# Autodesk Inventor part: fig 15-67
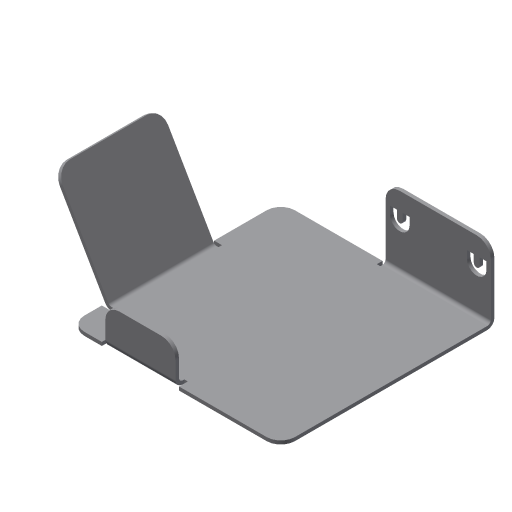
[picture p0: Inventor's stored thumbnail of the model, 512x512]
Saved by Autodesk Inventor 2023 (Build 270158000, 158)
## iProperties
Created: 2002-04
Part Number: fig 15-67
Document SubType Name: Sheet Metal
Density: 1 g/cm^3
Sheet Metal Rule: Default
Material: Generic
Appearance: Default
Control State: 0
Master: False
Checked Out: False
Shininess: 77.0
Angle Display Precision: 2
Document Length Units: 11269
Document Angle Units: 11279
Document Time Units: 11290
Document Mass Units: 11283
Document Length Units Precision: 3
Document Angle Units Precision: 2
Density: 0.0
Volumn: 0.0
Area: 0.0
PropertySet Name: Model Information
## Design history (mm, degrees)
node "Face1"
  sketch "Sketch1"
    geometry: L1 (12.647, 25.882)-(12.647, -14.118); L2 (12.647, -14.118)-(-17.353, -14.118); L3 (-17.353, -14.118)-(-17.353, 15.882); L4 (-17.353, 15.882)-(-2.353, 15.882); L5 (-2.353, 15.882)-(-2.353, 25.882); L6 (-2.353, 25.882)-(12.647, 25.882); 1 further point
    constraints: 12 end point, 4 parallel, 1 perpendicular
    dimensions: "d5" = 30 distance of L2.end L3.end; "d6" = 10 distance of L4.end L5.end; "d7" = 15 distance of L3.end L4.end; "d25" = 15 distance of L5.end L1.start
sketch "Sketch3"
  geometry: L1 (10, -15)-(10, 0)
  constraints: 2 end point
feature "Fold3" sketch "Sketch3" dims "d26" = 0.5 (= BendRadius), "d27" = 90 deg, "d28" = 0.5 (= BendRadius), "d96" = 0.5 (= BendReliefWidth), "d97" = 0.25 (= BendReliefDepth), "d98" = 1 (= MinimumRemnant), "d108" = 0.5 (= Thickness), "SeamGap" = 0.01
node "Flange2"
sketch "Sketch6"
  geometry: L1 (-6.914, 3.413)-(-5.843, 3.413); L2 (-5.843, 0.624)-(-6.914, 0.624); L3 (-6.914, 2.432)-(-5.843, 2.432); L4 (-5.843, 1.605)-(-6.914, 1.605); L5 (-6.914, 0.624)-(-6.914, 1.605); L6 (-6.914, 2.432)-(-6.914, 3.413); L7 (-6.914, 12.568)-(-6.914, 11.587); L8 (-6.914, 14.376)-(-6.914, 13.395); L9 (-6.914, 11.587)-(-5.843, 11.587); L10 (-5.843, 14.376)-(-6.914, 14.376); L11 (-6.914, 12.568)-(-5.843, 12.568); L12 (-5.843, 13.395)-(-6.914, 13.395); A1 r 1.394 centre (-5.843, 2.018) between (-5.843, 0.624) and (-5.843, 3.413); A2 r 0.413 centre (-5.843, 2.018) between (-5.843, 1.605) and (-5.843, 2.432); A3 r 1.394 centre (-5.843, 12.982) between (-5.843, 11.587) and (-5.843, 14.376); A4 r 0.413 centre (-5.843, 12.982) between (-5.843, 12.568) and (-5.843, 13.395)
  constraints: 24 end point, 8 point on circle, 4 centre point, 3 equal length, 1 perpendicular
cut "Cut1" sketch "Sketch6" dims "d49" = 0.5 (= Thickness), "d50" = 0
node "Flange3"
feature "Corner Round2" dims "d107" = 2
body "Solid1"
face "Plate1" dims "d108" = 0.5 (= Thickness)
sketch "Sketch5"
  geometry: L1 (20, 0)-(5, 0); L2 (5, 0)-(5, 15); L3 (5, 15)-(20, 15); L4 (20, 15)-(20, 0)
  constraints: 8 end point
face "Plate6" dims "d35" = 10, "d36" = 5, "d38" = 15, "d39" = 60 deg, "d40" = 0.5 (= BendRadius), "d108" = 0.5 (= Thickness), "MinimumRemnant" = 1 (= 2 x Thickness), "BendReliefWidth" = 0.5 (= Thickness)
bend "Bend5" dims "d38" = 15, "d39" = 60 deg, "d40" = 0.5 (= BendRadius), "d99" = 0.5 (= BendReliefWidth), "d100" = 0.25 (= BendReliefDepth), "d101" = 1 (= MinimumRemnant), "d108" = 0.5 (= Thickness), "SeamGap" = 0.01, "MinimumRemnant" = 1 (= 2 x Thickness), "BendReliefWidth" = 0.5 (= Thickness), "TransitionRadius" = 0.5 (= BendRadius)
sketch "Sketch7"
  geometry: L1 (25, 0)-(15, 0); L2 (15, 0)-(15, 5); L3 (15, 5)-(25, 5); L4 (25, 5)-(25, 0)
  constraints: 8 end point
face "Plate7" dims "d57" = 5, "d58" = 10, "d60" = 5, "d61" = 90 deg, "d62" = 0.5 (= BendRadius), "d108" = 0.5 (= Thickness), "MinimumRemnant" = 1 (= 2 x Thickness), "BendReliefWidth" = 0.5 (= Thickness)
bend "Bend7" dims "d59" = 0.5 (= BendRadius), "d60" = 5, "d61" = 90 deg, "d62" = 0.5 (= BendRadius), "d102" = 0.5 (= BendReliefWidth), "d103" = 0.25 (= BendReliefDepth), "d104" = 1 (= MinimumRemnant), "d108" = 0.5 (= Thickness), "SeamGap" = 0.01, "MinimumRemnant" = 1 (= 2 x Thickness), "BendReliefWidth" = 0.5 (= Thickness)
other parameters: "Thickness" = 0.5, "BendRadius" = 0.5 (= Thickness), "BendReliefDepth" = 0.25 (= 0.5 x Thickness), "CornerReliefSize" = 2 (= 4 x Thickness), "d0" = 0.5 (= BendRadius), "d13" = 0.5 (= BendRadius), "d31" = 0.5 (= BendRadius), "d37" = 0.5 (= BendRadius), "JacobiRadiusSize" = 0.5 (= Thickness), "GapSize" = 0.5 (= Thickness)
